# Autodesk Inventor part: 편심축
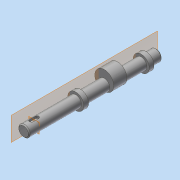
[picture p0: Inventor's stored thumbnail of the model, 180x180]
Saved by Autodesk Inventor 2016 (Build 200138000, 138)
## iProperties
Created: 2016-02
Part Number: 편심축
Material: 강철, 연강
Document SubType Name: Modeling
Designer: mduedu
Density: 1 g/cm^3
Appearance: 강철
Author: mduedu
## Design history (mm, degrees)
sketch "스케치1"
  geometry: C1 r 6 at (0, 0); 1 further point
  constraints: 1 centre point, 1 coincident
  dimensions: "d0" = 12 diameter of C1
extrude "돌출1" new body sketch "스케치1" distance "d1" = 140; taper "d2" = 0 deg
chamfer "모따기1" distance "d3" = 1; stored, may be unused: second distance "d4" = 2, angle "d5" = 45 deg
node "작업 평면1"
sketch "스케치2"
  geometry: C1 r 10 at (0, 4); C2 r 6 at (0, 0) reference; 1 further point
  constraints: 1 centre point, 1 tangent, 1 vertical alignment
  dimensions: "d7" = 20 diameter of C1
extrude "돌출2" join sketch "스케치2" stored distance "d8" = 14; taper "d9" = 0 deg
node "작업 평면2"
sketch "스케치3"
  geometry: C1 r 8.5 at (0, 0); 1 further point
  constraints: 1 centre point, 1 coincident
  dimensions: "d12" = 17 diameter of C1
extrude "돌출3" join sketch "스케치3" distance "d13" = 5; taper "d14" = 0 deg
node "작업 평면3"
sketch "스케치4"
  geometry: L1 (-5, 140)-(5, 140) reference; L2 (0, 140)-(0, 0); L3 (-2, 132)-(-2, 126); L4 (2, 126)-(2, 132); A1 r 2 centre (0, 132) between (2, 132) and (-2, 132); A2 r 2 centre (0, 126) between (-2, 126) and (2, 126)
  constraints: 6 end point, 4 point on circle, 4 tangent, 2 centre point, 2 point on line, 1 midpoint, 1 parallel, 1 perpendicular
  dimensions: "d15" = 4 distance between parallel lines of L3 L4; "d17" = 6 distance edge to line of A1 L1; "d18" = 10 dimension on A2 A1
extrude "돌출4" cut sketch "스케치4" distance "d19" = 2.5; taper "d20" = 0 deg
sketch "스케치5"
  geometry: L1 (6, 55)-(6, 139) reference; L2 (-6, 55)-(-6, 139) reference; L3 (6, 115)-(-6, 115); L4 (-5, 140)-(5, 140) reference; L5 (6, 116.5)-(4.5, 115); L6 (6, 116.5)-(6, 115); L7 (4.5, 115)-(6, 115); 1 further point
  constraints: 8 end point, 4 point on line, 2 collinear, 1 perpendicular
  dimensions: "d21" = 25 distance between parallel lines of L3 L4; "d22" = 3 diameter of L5.start L3; "d24" = 45 deg angle of L3 L5
revolve "회전1" sketch "스케치5" stored, may be unused: angle "d25" = 90 deg
sketch "스케치6"
  geometry: L1 (6, 116.5)-(4.5, 115) reference; L2 (6, 113.5)-(4.5, 115) reference; 2 further points
  constraints: 1 coincident
node "작업 평면4"
sketch "스케치7"
  geometry: C1 r 8.5 at (0, -4); 1 further point
  constraints: 1 centre point, 1 coincident
  dimensions: "d27" = 17 diameter of C1
extrude "돌출5" join sketch "스케치7" distance "d29" = 5; taper "d30" = 0 deg
node "작업 평면5"
node "작업 평면6"
node "솔리드1"
other parameters: "d6" = -48, "d11" = -11, "d31" = -11
